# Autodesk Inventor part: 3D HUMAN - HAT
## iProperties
Company: Cross Bros.
Shininess: 64.0
Length Units: 11272
Angle Units: 11279
Time Units: 11290
Mass Units: 11286
Length Display Precision: 3
Angle Display Precision: 2
Compacted: True
Part Number: 3D HUMAN - HAT
Document SubType Name: Modeling
Created: 2003-07
Designer: MVF
Manufacturer: Standard
Standards Organization: Custom
Catalog Web Link: www.crossbros.com
Density: 0.0
Volumn: 0.0
Area: 0.0
PropertySet Name: Model Information
Control State: 0
Master: False
Checked Out: False
Author: MVF
Title: iMike
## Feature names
1. Revolution1
2. Extrusion1
3. Mirror1
4. Extrusion2
5. Extrusion3
